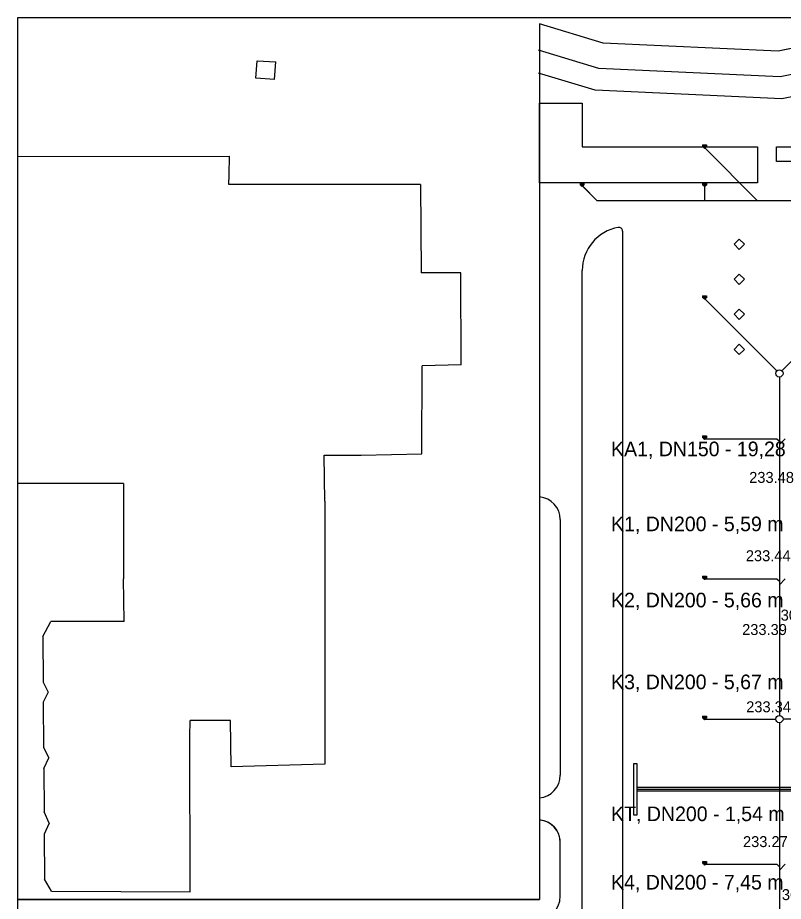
# Model space of a CAD drawing. Extents: x -264031 to -263588, y -1242281 to -1242059.
# Drawn here: x -264031 to -263926.1, y -1242179.7 to -1242058.7 of the extents above; entities that cross this region are included whole.
import ezdxf

# ---------------------------------------------------------------- set-up
doc = ezdxf.new("R2010")
doc.units = 0
for name, color, linetype in [('KFA_2D_SITUACIA_DSP', 7, 'Continuous'), ('KFA_BODY_CISLO', 7, 'Continuous'), ('KFA_BODY_VYSKA', 7, 'Continuous'), ('POPIS', 7, 'Continuous'), ('RAM_NA_TLAC_3xA4_1-750', 7, 'Continuous')]:
    doc.layers.add(name, color=color, linetype=linetype)

msp = doc.modelspace()

# ---------------------------------------------------------------- linework, layer by layer
at = {"layer": 'KFA_2D_SITUACIA_DSP'}
for p, q in [((-263959.47, -1242059.53), (-263959.47, -1242179.48)), ((-263950.75, -1242062.15), (-263959.47, -1242059.53)), ((-263915.2, -1242060.92), (-263926.77, -1242063.25)), ((-263926.77, -1242063.25), (-263950.75, -1242062.15)), ((-263998.36, -1242066.98), (-263998.17, -1242064.57)), ((-263998.17, -1242064.57), (-263995.59, -1242064.72)), ((-263995.79, -1242067.14), (-263995.59, -1242064.72)), ((-263995.79, -1242067.14), (-263998.36, -1242066.98)), ((-263959.47, -1242071.38), (-263959.47, -1242070.38)), ((-263959.47, -1242070.38), (-263953.62, -1242070.38)), ((-263953.62, -1242070.38), (-263953.62, -1242076.38)), ((-263959.47, -1242076.38), (-263959.47, -1242071.38)), ((-263959.47, -1242081.31), (-263959.47, -1242076.38)), ((-263953.62, -1242076.38), (-263929.58, -1242076.38)), ((-263937.09, -1242076.38), (-263937.09, -1242076.09)), ((-263937.09, -1242076.09), (-263936.59, -1242076.09)), ((-263936.59, -1242076.38), (-263937.09, -1242076.09)), ((-263936.59, -1242076.38), (-263937.09, -1242076.09)), ((-263937.09, -1242076.09), (-263937.09, -1242076.38)), ((-263936.59, -1242076.38), (-263937.09, -1242076.38)), ((-263937.09, -1242076.38), (-263936.59, -1242076.38)), ((-263936.77, -1242076.55), (-263929.63, -1242083.7)), ((-263936.59, -1242076.09), (-263936.59, -1242076.38)), ((-263929.58, -1242076.38), (-263929.58, -1242081.31)), ((-263926.97, -1242076.38), (-263921.97, -1242076.38)), ((-263926.97, -1242078.38), (-263926.97, -1242076.38)), ((-263926.97, -1242076.38), (-263926.97, -1242076.38)), ((-264030.99, -1242077.68), (-264001.95, -1242077.64)), ((-264002.01, -1242080.21), (-264001.95, -1242077.64)), ((-263921.97, -1242078.38), (-263926.97, -1242078.38)), ((-264002.04, -1242081.51), (-264002.01, -1242080.21)), ((-263975.78, -1242081.51), (-264002.04, -1242081.51)), ((-263975.78, -1242081.51), (-263975.68, -1242093.61)), ((-263953.62, -1242081.31), (-263959.47, -1242081.31)), ((-263953.87, -1242081.6), (-263953.87, -1242081.31)), ((-263953.87, -1242081.31), (-263953.37, -1242081.31)), ((-263953.37, -1242081.6), (-263953.87, -1242081.31)), ((-263953.37, -1242081.6), (-263953.87, -1242081.31)), ((-263953.87, -1242081.31), (-263953.87, -1242081.6)), ((-263953.37, -1242081.6), (-263953.87, -1242081.6)), ((-263953.87, -1242081.6), (-263953.37, -1242081.6)), ((-263929.58, -1242081.31), (-263953.62, -1242081.31)), ((-263953.62, -1242081.7), (-263951.62, -1242083.7)), ((-263953.55, -1242081.77), (-263951.62, -1242083.7)), ((-263953.37, -1242081.31), (-263953.37, -1242081.6)), ((-263937.09, -1242081.6), (-263937.09, -1242081.31)), ((-263937.09, -1242081.31), (-263936.59, -1242081.31)), ((-263936.59, -1242081.6), (-263937.09, -1242081.31)), ((-263936.59, -1242081.6), (-263937.09, -1242081.31)), ((-263937.09, -1242081.31), (-263937.09, -1242081.6)), ((-263936.59, -1242081.6), (-263937.09, -1242081.6)), ((-263937.09, -1242081.6), (-263936.59, -1242081.6)), ((-263936.59, -1242081.31), (-263936.59, -1242081.6)), ((-263936.84, -1242081.8), (-263936.84, -1242083.7)), ((-263951.62, -1242083.7), (-263918.81, -1242083.7)), ((-263948.09, -1242087.9), (-263948.09, -1242241.46)), ((-263932.8, -1242089.71), (-263932.09, -1242089)), ((-263932.09, -1242089), (-263931.39, -1242089.71)), ((-263932.09, -1242089), (-263932.09, -1242089)), ((-263932.09, -1242090.41), (-263932.8, -1242089.71)), ((-263931.39, -1242089.71), (-263932.09, -1242090.41)), ((-263970.24, -1242093.63), (-263975.68, -1242093.61)), ((-263970.22, -1242106.22), (-263970.24, -1242093.63)), ((-263953.62, -1242244.46), (-263953.62, -1242093.31)), ((-263932.8, -1242094.51), (-263932.09, -1242093.8)), ((-263932.09, -1242093.8), (-263931.39, -1242094.51)), ((-263932.09, -1242093.8), (-263932.09, -1242093.8)), ((-263932.09, -1242095.21), (-263932.8, -1242094.51)), ((-263931.39, -1242094.51), (-263932.09, -1242095.21)), ((-263937.09, -1242097.05), (-263937.09, -1242096.76)), ((-263937.09, -1242096.76), (-263936.59, -1242096.76)), ((-263936.59, -1242097.05), (-263937.09, -1242096.76)), ((-263936.59, -1242097.05), (-263937.09, -1242096.76)), ((-263937.09, -1242096.76), (-263937.09, -1242097.05)), ((-263936.59, -1242097.05), (-263937.09, -1242097.05)), ((-263937.09, -1242097.05), (-263936.59, -1242097.05)), ((-263936.77, -1242097.22), (-263926.95, -1242107.05)), ((-263936.59, -1242096.76), (-263936.59, -1242097.05)), ((-263916.41, -1242097.22), (-263926.24, -1242107.05)), ((-263932.8, -1242099.31), (-263932.09, -1242098.6)), ((-263932.09, -1242098.6), (-263931.39, -1242099.31)), ((-263932.09, -1242098.6), (-263932.09, -1242098.6)), ((-263932.09, -1242100.01), (-263932.8, -1242099.31)), ((-263931.39, -1242099.31), (-263932.09, -1242100.01)), ((-263932.8, -1242104.11), (-263932.09, -1242103.4)), ((-263932.09, -1242103.4), (-263931.39, -1242104.11)), ((-263932.09, -1242103.4), (-263932.09, -1242103.4)), ((-263932.09, -1242104.81), (-263932.8, -1242104.11)), ((-263931.39, -1242104.11), (-263932.09, -1242104.81)), ((-263975.61, -1242118.44), (-263975.57, -1242106.38)), ((-263970.22, -1242106.22), (-263975.57, -1242106.38)), ((-263926.59, -1242107.9), (-263926.59, -1242154.25)), ((-263926.59, -1242107.9), (-263926.59, -1242154.25)), ((-263937.09, -1242116.25), (-263937.09, -1242115.96)), ((-263937.09, -1242115.96), (-263936.59, -1242115.96)), ((-263936.59, -1242116.25), (-263937.09, -1242115.96)), ((-263936.59, -1242116.25), (-263937.09, -1242115.96)), ((-263937.09, -1242115.96), (-263937.09, -1242116.25)), ((-263936.59, -1242116.25), (-263937.09, -1242116.25)), ((-263937.09, -1242116.25), (-263936.59, -1242116.25)), ((-263936.74, -1242116.35), (-263926.95, -1242116.35)), ((-263936.59, -1242115.96), (-263936.59, -1242116.25)), ((-263926.95, -1242116.35), (-263926.59, -1242116.68)), ((-263925.8, -1242116.35), (-263926.59, -1242117.15)), ((-263989, -1242118.61), (-263983.93, -1242118.61)), ((-263988.88, -1242124.89), (-263989, -1242118.61)), ((-263983.93, -1242118.61), (-263975.61, -1242118.44)), ((-264016.48, -1242122.48), (-264030.99, -1242122.49)), ((-264016.48, -1242122.48), (-264016.47, -1242135.53)), ((-263988.88, -1242124.89), (-263988.91, -1242160.93)), ((-263959.47, -1242124.32), (-263959.47, -1242124.32)), ((-263956.62, -1242127.42), (-263956.62, -1242162.45)), ((-264016.38, -1242141.37), (-264016.47, -1242135.53)), ((-263937.09, -1242135.45), (-263937.09, -1242135.16)), ((-263937.09, -1242135.16), (-263936.59, -1242135.16)), ((-263936.59, -1242135.45), (-263937.09, -1242135.16)), ((-263936.59, -1242135.45), (-263937.09, -1242135.16)), ((-263937.09, -1242135.16), (-263937.09, -1242135.45)), ((-263936.59, -1242135.45), (-263937.09, -1242135.45)), ((-263937.09, -1242135.45), (-263936.59, -1242135.45)), ((-263936.74, -1242135.55), (-263926.95, -1242135.55)), ((-263936.59, -1242135.16), (-263936.59, -1242135.45)), ((-263926.95, -1242135.55), (-263926.59, -1242135.88)), ((-263925.8, -1242135.55), (-263926.59, -1242136.35)), ((-264027.55, -1242143.43), (-264026.42, -1242141.41)), ((-264016.38, -1242141.37), (-264026.42, -1242141.41)), ((-264027.55, -1242143.43), (-264027.5, -1242149.68)), ((-264027.5, -1242149.68), (-264026.79, -1242151.05)), ((-264026.79, -1242151.05), (-264027.48, -1242152.43)), ((-264027.48, -1242152.43), (-264027.43, -1242158.63)), ((-263937.09, -1242154.65), (-263937.09, -1242154.36)), ((-263937.09, -1242154.36), (-263936.59, -1242154.36)), ((-263936.59, -1242154.65), (-263937.09, -1242154.36)), ((-263936.59, -1242154.65), (-263937.09, -1242154.36)), ((-263937.09, -1242154.36), (-263937.09, -1242154.65)), ((-263936.59, -1242154.36), (-263936.59, -1242154.65)), ((-264007.37, -1242157.14), (-264007.36, -1242154.93)), ((-264001.8, -1242154.96), (-264007.36, -1242154.93)), ((-264001.73, -1242161.29), (-264001.8, -1242154.96)), ((-263936.59, -1242154.65), (-263937.09, -1242154.65)), ((-263937.09, -1242154.65), (-263936.59, -1242154.65)), ((-263936.74, -1242154.75), (-263927.09, -1242154.75)), ((-263926.59, -1242155.25), (-263926.59, -1242204.25)), ((-263920.94, -1242154.75), (-263926.09, -1242154.75)), ((-264007.34, -1242178.42), (-264007.37, -1242157.14)), ((-264027.43, -1242158.63), (-264026.72, -1242160.07)), ((-264027.41, -1242161.52), (-264026.72, -1242160.07)), ((-264027.41, -1242161.52), (-264027.36, -1242167.48)), ((-263988.91, -1242160.93), (-264001.73, -1242161.29)), ((-263918.49, -1242164.13), (-263946.09, -1242164.13)), ((-263918.59, -1242164.38), (-263946.09, -1242164.38)), ((-263918.7, -1242164.63), (-263946.09, -1242164.63)), ((-263959.47, -1242165.55), (-263959.47, -1242165.55)), ((-264026.65, -1242168.99), (-264027.36, -1242167.48)), ((-263959.47, -1242168.58), (-263959.47, -1242168.58)), ((-264026.65, -1242168.99), (-264027.34, -1242170.52)), ((-264027.34, -1242170.52), (-264027.29, -1242176.68)), ((-263956.62, -1242178.98), (-263956.62, -1242171.65)), ((-263937.09, -1242174.55), (-263937.09, -1242174.26)), ((-263937.09, -1242174.26), (-263936.59, -1242174.26)), ((-263936.59, -1242174.55), (-263937.09, -1242174.26)), ((-263936.59, -1242174.55), (-263937.09, -1242174.26)), ((-263937.09, -1242174.26), (-263937.09, -1242174.55)), ((-263936.59, -1242174.55), (-263937.09, -1242174.55)), ((-263937.09, -1242174.55), (-263936.59, -1242174.55)), ((-263936.74, -1242174.65), (-263926.95, -1242174.65)), ((-263936.59, -1242174.26), (-263936.59, -1242174.55)), ((-263926.95, -1242174.65), (-263926.59, -1242174.98)), ((-263925.8, -1242174.65), (-263926.59, -1242175.45)), ((-264026.37, -1242178.31), (-264027.29, -1242176.68)), ((-264026.37, -1242178.31), (-264007.34, -1242178.42)), ((-263959.47, -1242179.48), (-264030.99, -1242179.48)), ((-264030.99, -1242179.48), (-263959.47, -1242179.48)), ((-263959.47, -1242179.48), (-264030.99, -1242179.48)), ((-263956.62, -1242178.98), (-263956.62, -1242178.98))]:
    msp.add_line(p, q, dxfattribs=at)
for points in [[(-263863.95, -1242065.11), (-263895.45, -1242062.32), (-263915.2, -1242060.92), (-263926.77, -1242063.25), (-263950.75, -1242062.15), (-263959.47, -1242059.53)], [(-263864.26, -1242068.59), (-263895.73, -1242065.81), (-263914.97, -1242064.45), (-263926.5, -1242066.77), (-263951.34, -1242065.63), (-263959.61, -1242063.14)], [(-263864.52, -1242071.58), (-263895.97, -1242068.8), (-263914.78, -1242067.47), (-263926.27, -1242069.78), (-263951.84, -1242068.6), (-263959.61, -1242066.28)], [(-263956.62, -1242178.98), (-263956.62, -1242171.63), (-263956.64, -1242171.26), (-263956.71, -1242170.89), (-263956.87, -1242170.41), (-263957.16, -1242169.89), (-263957.43, -1242169.55), (-263957.71, -1242169.29), (-263958.08, -1242169.02), (-263958.45, -1242168.83), (-263958.84, -1242168.69), (-263959.06, -1242168.64), (-263959.27, -1242168.6), (-263959.47, -1242168.58)]]:
    msp.add_lwpolyline(points, dxfattribs=at)
msp.add_lwpolyline([(-263946.09, -1242167.88), (-263946.09, -1242160.88), (-263946.59, -1242160.88), (-263946.59, -1242167.88)], close=True, dxfattribs=at)
for centre, radius in [((-263936.84, -1242076.48), 0.1), ((-263953.62, -1242081.7), 0.1), ((-263936.84, -1242081.7), 0.1), ((-263936.84, -1242097.15), 0.1), ((-263926.59, -1242107.4), 0.5), ((-263936.84, -1242116.35), 0.1), ((-263936.84, -1242135.55), 0.1), ((-263926.59, -1242154.75), 0.5), ((-263936.84, -1242154.75), 0.1), ((-263936.84, -1242174.65), 0.1)]:
    msp.add_circle(centre, radius, dxfattribs=at)
for centre, radius, start, end in [((-263947.63, -1242093.3), 5.98, 100.0694, 180.066), ((-263948.59, -1242087.9), 0.5, 0, 100.0694), ((-263959.74, -1242127.43), 3.12, 0.1518, 85.0363), ((-263959.74, -1242162.44), 3.12, 274.9637, 359.8482), ((-263959.67, -1242171.63), 3.05, 359.6441, 86.2155), ((-263960.12, -1242178.98), 3.5, 270, 0)]:
    msp.add_arc(centre, radius, start, end, dxfattribs=at)
at = {"layer": 'RAM_NA_TLAC_3xA4_1-750'}
msp.add_lwpolyline([(-264030.99, -1242281.43), (-263873.49, -1242281.43), (-263730.99, -1242281.43), (-263588.49, -1242281.43), (-263588.49, -1242058.68), (-263730.99, -1242058.68), (-263873.49, -1242058.68), (-264030.99, -1242058.68)], close=True, dxfattribs=at)

# ---------------------------------------------------------------- texts
at = {"layer": 'KFA_BODY_CISLO'}
for s, p in [('30', (-263926.41, -1242141.26)), ('36', (-263926.25, -1242179.55))]:
    msp.add_text(s, height=1.5, dxfattribs=at).set_placement(p)
at = {"layer": 'KFA_BODY_VYSKA'}
for s, p in [('233.48', (-263930.73, -1242122.4)), ('233.44', (-263931.19, -1242133.13)), ('233.39', (-263931.7, -1242143.24)), ('233.34', (-263931.14, -1242153.82)), ('233.27', (-263931.58, -1242172.29))]:
    msp.add_text(s, height=1.5, dxfattribs=at).set_placement(p)
at = {"layer": 'POPIS'}
for s, p in [('KA1, DN150 - 19,28 m', (-263949.66, -1242118.75)), ('K1, DN200 - 5,59 m', (-263949.66, -1242129.02)), ('K2, DN200 - 5,66 m', (-263949.66, -1242139.45)), ('K3, DN200 - 5,67 m', (-263949.66, -1242150.66)), ('KT, DN200 - 1,54 m', (-263949.66, -1242168.73)), ('K4, DN200 - 7,45 m', (-263949.66, -1242178.1))]:
    msp.add_text(s, height=2, dxfattribs=at).set_placement(p)

doc.saveas('drawing.dxf')
